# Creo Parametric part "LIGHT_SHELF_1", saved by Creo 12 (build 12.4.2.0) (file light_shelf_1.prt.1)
Units: Custom; MM, KILOGRAM, SECS

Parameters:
  PTC_WM_ITERATION = "0"
  PTC_WM_VERSION = "-.0"
  PTC_WM_LIFECYCLE_STATE = "In Work"
  PTC_WM_LIFECYCLE = "MO_CADDocument"
  PTC_WM_CREATED_BY = "Maximilian Roepper (Z0017RMS: MO)"
  PTC_WM_CREATED_ON = "18-Sep-26 11:36:42 AM"
  PTC_WM_MODIFIED_BY = "Maximilian Roepper (Z0017RMS: MO)"
  PTC_WM_MODIFIED_ON = "18-Sep-26 11:36:46 AM"
  PDMLINKNUMBER = "PDM000071454791"
  PTC_WM_NAME = "light_shelf_1.prt"
  PTC_WM_NUMBER = "PDM000071454791"

Other parameters: WEIGHT, WEIGHT_FACTOR, WEIGHT_ADD, _MASS_TEMP, _DIFF_TEMP, MC_ERRORS, SUPPLIER

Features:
  1. coordinate system
  2. datum plane "PRT_YZ"
  3. datum plane "PRT_XY"
  4. datum plane "PRT_XZ"
  5. coordinate system
  6. datum axis
  7. datum axis
  8. datum axis
  9. coordinate system
  10. imported feature

Other named items: PRT, SIEMENS_MO, DRW_VIEW_ORG, PRT_X, PRT_Y, PRT_Z, CS0, ROUGH_GROB

Layers: 00_STD_CSYS-KSYS, 01_STD_PLANES-EBENEN, 02_STD_AXES-ACHSEN, 03_STD_CSYS-KSYS, 24_IMPORT_FEAT-IMPORT_KE

Surfaces: 18 plane, 4 cylinder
